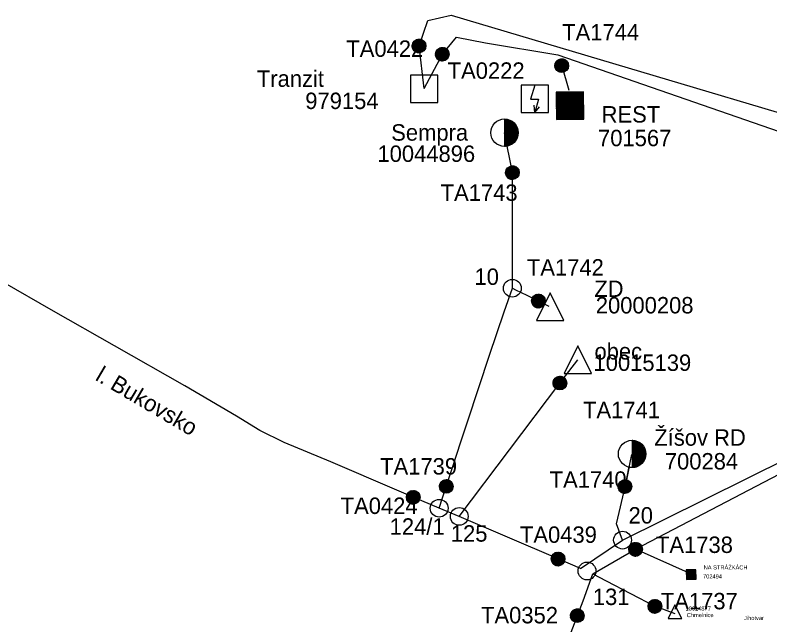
# Model space of a CAD drawing. Extents: x -749194 to -734612, y -1146817 to -1138558.
# Drawn here: x -738789 to -736032, y -1144443 to -1142216 of the extents above; entities that cross this region are included whole.
import ezdxf

# ---------------------------------------------------------------- set-up
doc = ezdxf.new("R2010")
doc.units = 0
for name, color, linetype in [('Default', 7, 'Continuous'), ('Vrstva 1', 7, 'Continuous'), ('Vrstva 2', 7, 'Continuous'), ('Vrstva 20', 7, 'Continuous'), ('Vrstva 3', 7, 'Continuous'), ('Vrstva 4', 7, 'Continuous'), ('Vrstva 44', 7, 'Continuous'), ('Vrstva 47', 7, 'Continuous'), ('Vrstva 5', 7, 'Continuous')]:
    doc.layers.add(name, color=color, linetype=linetype)

# ---------------------------------------------------------------- blocks, each defined once
blk = doc.blocks.new('PS705')
at = {"layer": 'Vrstva 47'}
for points in [[(50, 50), (-50, 50)], [(-50, 50), (-50, -50)], [(0, 50), (-15.8, -0.8)], [(50, -50), (50, 50)], [(-15.8, -0.8), (14.2, -0.8)], [(0, -50), (-2.8, -22.8)], [(14.2, -0.8), (0, -50)], [(-50, -50), (50, -50)], [(0, -50), (17.3, -28.3)]]:
    blk.add_lwpolyline(points, dxfattribs=at)
blk = doc.blocks.new('PS400')
at = {"layer": 'Default'}
for p, q in [((-25, 0.1), (-0.1, 25)), ((-24.9, -1.2), (1.2, 24.9)), ((-24.9, 1.6), (-1.6, 24.9)), ((-24.8, -2.6), (2.6, 24.8)), ((-24.8, 3.2), (-3.2, 24.8)), ((-24.7, -3.8), (3.8, 24.7)), ((-24.5, -5), (5, 24.5)), ((-24.5, 4.9), (-4.9, 24.5)), ((-24.2, -6.2), (6.2, 24.2)), ((-24.1, 6.7), (-6.7, 24.1)), ((-23.9, -7.3), (7.3, 23.9)), ((-23.6, -8.3), (8.3, 23.6)), ((-23.4, 8.8), (-8.8, 23.4)), ((-23.2, -9.4), (9.4, 23.2)), ((-22.7, -10.3), (10.3, 22.7)), ((-22.3, -11.3), (11.3, 22.3)), ((-22.3, 11.3), (-11.3, 22.3)), ((-21.8, -12.2), (12.2, 21.8)), ((-21.3, -13.1), (13.1, 21.3)), ((-20.7, -14), (14, 20.7)), ((-20.1, -14.8), (14.8, 20.1)), ((-19.9, 15.2), (-15.2, 19.9)), ((-19.5, -15.6), (15.6, 19.5)), ((-18.9, -16.4), (16.4, 18.9)), ((-18.2, -17.1), (17.1, 18.2)), ((-17.5, -17.8), (17.8, 17.5)), ((-16.8, -18.5), (18.5, 16.8)), ((-16, -19.2), (19.2, 16)), ((-15.2, -19.8), (19.8, 15.2)), ((-14.4, -20.4), (20.4, 14.4)), ((-13.6, -21), (21, 13.6)), ((-12.7, -21.5), (21.5, 12.7)), ((-11.8, -22), (22, 11.8)), ((-10.8, -22.5), (22.5, 10.8)), ((-9.9, -22.9), (22.9, 9.9)), ((-8.9, -23.4), (23.4, 8.9)), ((-7.8, -23.7), (23.7, 7.8)), ((-6.7, -24.1), (24.1, 6.7)), ((-5.6, -24.3), (24.3, 5.6)), ((-4.4, -24.6), (24.6, 4.4)), ((-3.2, -24.8), (24.8, 3.2)), ((-1.9, -24.9), (24.9, 1.9)), ((-0.6, -25), (25, 0.6)), ((0.8, -25), (25, -0.8)), ((2.3, -24.9), (24.9, -2.3)), ((4, -24.7), (24.7, -4)), ((5.7, -24.3), (24.3, -5.7)), ((7.7, -23.8), (23.8, -7.7)), ((10, -22.9), (22.9, -10)), ((12.9, -21.4), (21.4, -12.9))]:
    blk.add_line(p, q, dxfattribs=at)
blk.add_circle((0, 0), 25, dxfattribs=at)
blk = doc.blocks.new('PS440')
at = {"layer": 'Default'}
for p, q in [((-25, 0.1), (-0.1, 25)), ((-24.9, -1.2), (1.2, 24.9)), ((-24.9, 1.6), (-1.6, 24.9)), ((-24.8, -2.6), (2.6, 24.8)), ((-24.8, 3.2), (-3.2, 24.8)), ((-24.7, -3.8), (3.8, 24.7)), ((-24.5, -5), (5, 24.5)), ((-24.5, 4.9), (-4.9, 24.5)), ((-24.2, -6.2), (6.2, 24.2)), ((-24.1, 6.7), (-6.7, 24.1)), ((-23.9, -7.3), (7.3, 23.9)), ((-23.6, -8.3), (8.3, 23.6)), ((-23.4, 8.8), (-8.8, 23.4)), ((-23.2, -9.4), (9.4, 23.2)), ((-22.7, -10.3), (10.3, 22.7)), ((-22.3, -11.3), (11.3, 22.3)), ((-22.3, 11.3), (-11.3, 22.3)), ((-21.8, -12.2), (12.2, 21.8)), ((-21.3, -13.1), (13.1, 21.3)), ((-20.7, -14), (14, 20.7)), ((-20.1, -14.8), (14.8, 20.1)), ((-19.9, 15.2), (-15.2, 19.9)), ((-19.5, -15.6), (15.6, 19.5)), ((-18.9, -16.4), (16.4, 18.9)), ((-18.2, -17.1), (17.1, 18.2)), ((-17.5, -17.8), (17.8, 17.5)), ((-16.8, -18.5), (18.5, 16.8)), ((-16, -19.2), (19.2, 16)), ((-15.2, -19.8), (19.8, 15.2)), ((-14.4, -20.4), (20.4, 14.4)), ((-13.6, -21), (21, 13.6)), ((-12.7, -21.5), (21.5, 12.7)), ((-11.8, -22), (22, 11.8)), ((-10.8, -22.5), (22.5, 10.8)), ((-9.9, -22.9), (22.9, 9.9)), ((-8.9, -23.4), (23.4, 8.9)), ((-7.8, -23.7), (23.7, 7.8)), ((-6.7, -24.1), (24.1, 6.7)), ((-5.6, -24.3), (24.3, 5.6)), ((-4.4, -24.6), (24.6, 4.4)), ((-3.2, -24.8), (24.8, 3.2)), ((-1.9, -24.9), (24.9, 1.9)), ((-0.6, -25), (25, 0.6)), ((0.8, -25), (25, -0.8)), ((2.3, -24.9), (24.9, -2.3)), ((4, -24.7), (24.7, -4)), ((5.7, -24.3), (24.3, -5.7)), ((7.7, -23.8), (23.8, -7.7)), ((10, -22.9), (22.9, -10)), ((12.9, -21.4), (21.4, -12.9))]:
    blk.add_line(p, q, dxfattribs=at)
blk.add_circle((0, 0), 25, dxfattribs=at)
blk = doc.blocks.new('PS820')
at = {"layer": 'Vrstva 2'}
blk.add_circle((0, 0), 32.5, dxfattribs=at)
blk = doc.blocks.new('PS680')
at = {"layer": 'Vrstva 44'}
for points in [[(0, 25), (-25, -25)], [(25, -25), (0, 25)], [(-25, -25), (25, -25)]]:
    blk.add_lwpolyline(points, dxfattribs=at)
blk = doc.blocks.new('PS630')
at = {"layer": 'Default'}
for p, q in [((-16.6, -14.9), (17.1, 18.7)), ((-16.6, -13.5), (15.7, 18.7)), ((-16.6, -12.1), (14.2, 18.7)), ((-16.6, -10.7), (12.8, 18.7)), ((-16.6, -9.3), (11.4, 18.7)), ((-16.6, -7.9), (10, 18.7)), ((-16.6, -6.5), (8.6, 18.7)), ((-16.6, -5), (7.2, 18.7)), ((-16.6, -3.6), (5.8, 18.7)), ((-16.6, -2.2), (4.3, 18.7)), ((-16.6, -0.8), (2.9, 18.7)), ((-16.6, 0.6), (1.5, 18.7)), ((-16.6, 2), (0.1, 18.7)), ((-16.6, 3.4), (-1.3, 18.7)), ((-16.6, 4.9), (-2.7, 18.7)), ((-16.6, 6.3), (-4.1, 18.7)), ((-16.6, 7.7), (-5.6, 18.7)), ((-16.6, 9.1), (-7, 18.7)), ((-16.6, 10.5), (-8.4, 18.7)), ((-16.6, 11.9), (-9.8, 18.7)), ((-16.6, 13.3), (-11.2, 18.7)), ((-16.6, 14.8), (-12.6, 18.7)), ((-16.6, 16.2), (-14, 18.7)), ((-16.6, 17.6), (-15.5, 18.7)), ((-16.5, -16.3), (18.4, 18.6)), ((-15.1, -16.3), (18.4, 17.2)), ((-13.7, -16.3), (18.4, 15.8)), ((-12.3, -16.3), (18.4, 14.4)), ((-10.9, -16.3), (18.4, 13)), ((-9.4, -16.3), (18.4, 11.6)), ((-8, -16.3), (18.4, 10.2)), ((-6.6, -16.3), (18.4, 8.7)), ((-5.2, -16.3), (18.4, 7.3)), ((-3.8, -16.3), (18.4, 5.9)), ((-2.4, -16.3), (18.4, 4.5)), ((-1, -16.3), (18.4, 3.1)), ((0.5, -16.3), (18.4, 1.7)), ((1.9, -16.3), (18.4, 0.3)), ((3.3, -16.3), (18.4, -1.2)), ((4.7, -16.3), (18.4, -2.6)), ((6.1, -16.3), (18.4, -4)), ((7.5, -16.3), (18.4, -5.4)), ((8.9, -16.3), (18.4, -6.8)), ((10.4, -16.3), (18.4, -8.2)), ((11.8, -16.3), (18.4, -9.6)), ((13.2, -16.3), (18.4, -11.1)), ((14.6, -16.3), (18.4, -12.5)), ((16, -16.3), (18.4, -13.9)), ((17.4, -16.3), (18.4, -15.3))]:
    blk.add_line(p, q, dxfattribs=at)
for points in [[(-16.6, 18.7), (-16.6, -16.3)], [(18.4, 18.7), (-16.6, 18.7)], [(-16.6, 18.7), (-16.6, -16.3)], [(18.4, -16.3), (18.4, 18.7)], [(-16.6, -16.3), (18.4, -16.3)]]:
    blk.add_lwpolyline(points, dxfattribs=at)
blk = doc.blocks.new('PS615')
at = {"layer": 'Default'}
for p, q in [((0, 49.1), (0.9, 50)), ((0, 46.3), (3.6, 49.9)), ((0, 47.7), (2.3, 49.9)), ((0, 44.8), (4.9, 49.8)), ((0, 43.4), (6.2, 49.6)), ((0, 42), (7.4, 49.4)), ((0, 40.6), (8.7, 49.2)), ((0, 39.2), (9.8, 49)), ((0, 37.8), (11, 48.8)), ((0, 36.4), (12.1, 48.5)), ((0, 34.9), (13.3, 48.2)), ((0, 33.5), (14.4, 47.9)), ((0, 32.1), (15.4, 47.6)), ((0, 30.7), (16.5, 47.2)), ((0, 29.3), (17.5, 46.8)), ((0, 27.9), (18.6, 46.4)), ((0, 26.5), (19.6, 46)), ((0, 25), (20.5, 45.6)), ((0, 23.6), (21.5, 45.1)), ((0, 22.2), (22.5, 44.7)), ((0, 20.8), (23.4, 44.2)), ((0, 19.4), (24.3, 43.7)), ((0, 18), (25.2, 43.2)), ((0, 16.6), (26.1, 42.6)), ((0, 15.1), (27, 42.1)), ((0, 13.7), (27.8, 41.5)), ((0, 12.3), (28.7, 41)), ((0, 10.9), (29.5, 40.4)), ((0, 9.5), (30.3, 39.8)), ((0, 8.1), (31.1, 39.2)), ((0, 6.7), (31.9, 38.5)), ((0, 5.2), (32.6, 37.9)), ((0, 3.8), (33.4, 37.2)), ((0, 2.4), (34.1, 36.5)), ((0, 1), (34.9, 35.9)), ((0, -0.4), (35.6, 35.1)), ((0, -1.8), (36.3, 34.4)), ((0, -3.2), (36.9, 33.7)), ((0, -4.7), (37.6, 32.9)), ((0, -6.1), (38.3, 32.2)), ((0, -7.5), (38.9, 31.4)), ((0, -8.9), (39.5, 30.6)), ((0, -10.3), (40.1, 29.8)), ((0, -11.7), (40.7, 29)), ((0, -13.1), (41.3, 28.2)), ((0, -14.6), (41.9, 27.3)), ((0, -16), (42.4, 26.5)), ((0, -17.4), (43, 25.6)), ((0, -18.8), (43.5, 24.7)), ((0, -20.2), (44, 23.8)), ((0, -21.6), (44.5, 22.8)), ((0, -23), (44.9, 21.9)), ((0, -24.5), (45.4, 20.9)), ((0, -25.9), (45.8, 20)), ((0, -27.3), (46.3, 19)), ((0, -28.7), (46.7, 18)), ((0, -30.1), (47, 16.9)), ((0, -31.5), (47.4, 15.9)), ((0, -32.9), (47.8, 14.8)), ((0, -34.4), (48.1, 13.7)), ((0, -35.8), (48.4, 12.6)), ((0, -37.2), (48.7, 11.5)), ((0, -38.6), (48.9, 10.3)), ((0, -40), (49.2, 9.1)), ((0, -41.4), (49.4, 7.9)), ((0, -42.8), (49.5, 6.7)), ((0, -44.3), (49.7, 5.4)), ((0, -45.7), (49.8, 4.2)), ((0, -47.1), (49.9, 2.8)), ((0, -48.5), (50, 1.5)), ((0, -49.9), (50, 0.1)), ((1.3, -50), (50, -1.3)), ((2.8, -49.9), (49.9, -2.8)), ((4.3, -49.8), (49.8, -4.3)), ((5.9, -49.6), (49.6, -5.9)), ((7.6, -49.4), (49.4, -7.6)), ((9.3, -49.1), (49.1, -9.3)), ((11.1, -48.8), (48.8, -11.1)), ((12.9, -48.3), (48.3, -12.9)), ((14.9, -47.7), (47.7, -14.9)), ((17.1, -47), (47, -17.1)), ((19.4, -46.1), (46.1, -19.4)), ((22, -44.9), (44.9, -22)), ((25, -43.3), (43.3, -25)), ((28.9, -40.8), (40.8, -28.9))]:
    blk.add_line(p, q, dxfattribs=at)
blk.add_lwpolyline([(0, 50), (0, -50)], dxfattribs=at)
blk.add_circle((0, 0), 50, dxfattribs=at)
blk = doc.blocks.new('PS685')
at = {"layer": 'Vrstva 44'}
for points in [[(-0.1, 50.1), (-50.1, -49.9)], [(49.9, -49.9), (-0.1, 50.1)], [(-50.1, -49.9), (49.9, -49.9)]]:
    blk.add_lwpolyline(points, dxfattribs=at)
blk = doc.blocks.new('PS656')
at = {"layer": 'Vrstva 20'}
for points in [[(49.9, 50.1), (-50.1, 50.1)], [(-50.1, 50.1), (-50.1, -49.9)], [(49.9, -49.9), (49.9, 50.1)], [(-50.1, -49.9), (49.9, -49.9)]]:
    blk.add_lwpolyline(points, dxfattribs=at)
blk = doc.blocks.new('PS636')
at = {"layer": 'Default'}
for p, q in [((-50.6, -54.9), (49, 44.7)), ((-50.6, -53.5), (47.6, 44.7)), ((-50.6, -52), (46.2, 44.7)), ((-50.6, -50.6), (44.7, 44.7)), ((-50.6, -49.2), (43.3, 44.7)), ((-50.6, -47.8), (41.9, 44.7)), ((-50.6, -46.4), (40.5, 44.7)), ((-50.6, -45), (39.1, 44.7)), ((-50.6, -43.6), (37.7, 44.7)), ((-50.6, -42.1), (36.3, 44.7)), ((-50.6, -40.7), (34.8, 44.7)), ((-50.6, -39.3), (33.4, 44.7)), ((-50.6, -37.9), (32, 44.7)), ((-50.6, -36.5), (30.6, 44.7)), ((-50.6, -35.1), (29.2, 44.7)), ((-50.6, -33.7), (27.8, 44.7)), ((-50.6, -32.2), (26.4, 44.7)), ((-50.6, -30.8), (24.9, 44.7)), ((-50.6, -29.4), (23.5, 44.7)), ((-50.6, -28), (22.1, 44.7)), ((-50.6, -26.6), (20.7, 44.7)), ((-50.6, -25.2), (19.3, 44.7)), ((-50.6, -23.8), (17.9, 44.7)), ((-50.6, -22.3), (16.5, 44.7)), ((-50.6, -20.9), (15, 44.7)), ((-50.6, -19.5), (13.6, 44.7)), ((-50.6, -18.1), (12.2, 44.7)), ((-50.6, -16.7), (10.8, 44.7)), ((-50.6, -15.3), (9.4, 44.7)), ((-50.6, -13.9), (8, 44.7)), ((-50.6, -12.4), (6.6, 44.7)), ((-50.6, -11), (5.1, 44.7)), ((-50.6, -9.6), (3.7, 44.7)), ((-50.6, -8.2), (2.3, 44.7)), ((-50.6, -6.8), (0.9, 44.7)), ((-50.6, -5.4), (-0.5, 44.7)), ((-50.6, -4), (-1.9, 44.7)), ((-50.6, -2.5), (-3.3, 44.7)), ((-50.6, -1.1), (-4.8, 44.7)), ((-50.6, 0.3), (-6.2, 44.7)), ((-50.6, 1.7), (-7.6, 44.7)), ((-50.6, 3.1), (-9, 44.7)), ((-50.6, 4.5), (-10.4, 44.7)), ((-50.6, 5.9), (-11.8, 44.7)), ((-50.6, 7.4), (-13.2, 44.7)), ((-50.6, 8.8), (-14.7, 44.7)), ((-50.6, 10.2), (-16.1, 44.7)), ((-50.6, 11.6), (-17.5, 44.7)), ((-50.6, 13), (-18.9, 44.7)), ((-50.6, 14.4), (-20.3, 44.7)), ((-50.6, 15.8), (-21.7, 44.7)), ((-50.6, 17.3), (-23.1, 44.7)), ((-50.6, 18.7), (-24.6, 44.7)), ((-50.6, 20.1), (-26, 44.7)), ((-50.6, 21.5), (-27.4, 44.7)), ((-50.6, 22.9), (-28.8, 44.7)), ((-50.6, 24.3), (-30.2, 44.7)), ((-50.6, 25.7), (-31.6, 44.7)), ((-50.6, 27.2), (-33, 44.7)), ((-50.6, 28.6), (-34.5, 44.7)), ((-50.6, 30), (-35.9, 44.7)), ((-50.6, 31.4), (-37.3, 44.7)), ((-50.6, 32.8), (-38.7, 44.7)), ((-50.6, 34.2), (-40.1, 44.7)), ((-50.6, 35.6), (-41.5, 44.7)), ((-50.6, 37.1), (-42.9, 44.7)), ((-50.6, 38.5), (-44.3, 44.7)), ((-50.6, 39.9), (-45.8, 44.7)), ((-50.6, 41.3), (-47.2, 44.7)), ((-50.6, 42.7), (-48.6, 44.7)), ((-50.6, 44.1), (-50, 44.7)), ((-49.6, -55.3), (49.4, 43.7)), ((-48.2, -55.3), (49.4, 42.3)), ((-46.8, -55.3), (49.4, 40.9)), ((-45.4, -55.3), (49.4, 39.5)), ((-43.9, -55.3), (49.4, 38.1)), ((-42.5, -55.3), (49.4, 36.6)), ((-41.1, -55.3), (49.4, 35.2)), ((-39.7, -55.3), (49.4, 33.8)), ((-38.3, -55.3), (49.4, 32.4)), ((-36.9, -55.3), (49.4, 31)), ((-35.5, -55.3), (49.4, 29.6)), ((-34, -55.3), (49.4, 28.2)), ((-32.6, -55.3), (49.4, 26.7)), ((-31.2, -55.3), (49.4, 25.3)), ((-29.8, -55.3), (49.4, 23.9)), ((-28.4, -55.3), (49.4, 22.5)), ((-27, -55.3), (49.4, 21.1)), ((-25.6, -55.3), (49.4, 19.7)), ((-24.1, -55.3), (49.4, 18.3)), ((-22.7, -55.3), (49.4, 16.8)), ((-21.3, -55.3), (49.4, 15.4)), ((-19.9, -55.3), (49.4, 14)), ((-18.5, -55.3), (49.4, 12.6)), ((-17.1, -55.3), (49.4, 11.2)), ((-15.7, -55.3), (49.4, 9.8)), ((-14.2, -55.3), (49.4, 8.4)), ((-12.8, -55.3), (49.4, 6.9)), ((-11.4, -55.3), (49.4, 5.5)), ((-10, -55.3), (49.4, 4.1)), ((-8.6, -55.3), (49.4, 2.7)), ((-7.2, -55.3), (49.4, 1.3)), ((-5.8, -55.3), (49.4, -0.1)), ((-4.3, -55.3), (49.4, -1.5)), ((-2.9, -55.3), (49.4, -2.9)), ((-1.5, -55.3), (49.4, -4.4)), ((-0.1, -55.3), (49.4, -5.8)), ((1.3, -55.3), (49.4, -7.2)), ((2.7, -55.3), (49.4, -8.6)), ((4.1, -55.3), (49.4, -10)), ((5.6, -55.3), (49.4, -11.4)), ((7, -55.3), (49.4, -12.8)), ((8.4, -55.3), (49.4, -14.3)), ((9.8, -55.3), (49.4, -15.7)), ((11.2, -55.3), (49.4, -17.1)), ((12.6, -55.3), (49.4, -18.5)), ((14, -55.3), (49.4, -19.9)), ((15.5, -55.3), (49.4, -21.3)), ((16.9, -55.3), (49.4, -22.7)), ((18.3, -55.3), (49.4, -24.2)), ((19.7, -55.3), (49.4, -25.6)), ((21.1, -55.3), (49.4, -27)), ((22.5, -55.3), (49.4, -28.4)), ((23.9, -55.3), (49.4, -29.8)), ((25.4, -55.3), (49.4, -31.2)), ((26.8, -55.3), (49.4, -32.6)), ((28.2, -55.3), (49.4, -34.1)), ((29.6, -55.3), (49.4, -35.5)), ((31, -55.3), (49.4, -36.9)), ((32.4, -55.3), (49.4, -38.3)), ((33.8, -55.3), (49.4, -39.7)), ((35.3, -55.3), (49.4, -41.1)), ((36.7, -55.3), (49.4, -42.5)), ((38.1, -55.3), (49.4, -44)), ((39.5, -55.3), (49.4, -45.4)), ((40.9, -55.3), (49.4, -46.8)), ((42.3, -55.3), (49.4, -48.2)), ((43.7, -55.3), (49.4, -49.6)), ((45.2, -55.3), (49.4, -51)), ((46.6, -55.3), (49.4, -52.4)), ((48, -55.3), (49.4, -53.9))]:
    blk.add_line(p, q, dxfattribs=at)
for points in [[(-50.6, 44.7), (-50.6, -55.3)], [(49.4, 44.7), (-50.6, 44.7)], [(-50.6, 44.7), (-50.6, -55.3)], [(49.4, -55.3), (49.4, 44.7)], [(-50.6, -55.3), (49.4, -55.3)]]:
    blk.add_lwpolyline(points, dxfattribs=at)

msp = doc.modelspace()

# ---------------------------------------------------------------- linework, layer by layer
at = {"layer": 'Vrstva 1'}
for points in [[(-737281.2, -1142235.6), (-737196, -1142216), (-735166, -1142820.5)], [(-737313.2, -1142328.7), (-737281.2, -1142235.6)], [(-737228.1, -1142358.7), (-737177, -1142296.1)], [(-737177, -1142296.1), (-737070.4, -1142317.6), (-736806.2, -1142360.9)], [(-737294.4, -1142484.2), (-737313.2, -1142328.7)], [(-737294, -1142484.2), (-737228.1, -1142358.7)], [(-736806.2, -1142360.9), (-735438.9, -1142834.9)], [(-736792, -1142400.7), (-736766.6, -1142490.2)], [(-736971.9, -1142791.4), (-737001.2, -1142645.4)], [(-737334.6, -1143976.8), (-737394.6, -1143951.2), (-737635.9, -1143848.1), (-737805.3, -1143777.2), (-737894.7, -1143733.3), (-737980.4, -1143680.5), (-738169, -1143569.6), (-738425.3, -1143423.7), (-738648.7, -1143297.5), (-738835.1, -1143190), (-738901.3, -1143150.6), (-738936.5, -1143130.2), (-738970.4, -1143109.9), (-739088.8, -1143046.1), (-739260.1, -1142910.3), (-739340.7, -1142846), (-739424.3, -1142779.4), (-739498, -1142714.4), (-739571.1, -1142649.7), (-739571.2, -1142649.6)], [(-736972.4, -1143213.6), (-736971.9, -1142791.4)], [(-736522.5, -1144166.6), (-735941.9, -1143863.1), (-735673.8, -1143252.7), (-734966.1, -1143033.7), (-734831.4, -1142984.5)], [(-736569.9, -1144133.5), (-735964, -1143832.7), (-735925.7, -1143729.5), (-735872.7, -1143602.7), (-735771, -1143349), (-735719.1, -1143221.8), (-735384.5, -1143105.6)], [(-737213.6, -1143937.5), (-737187.4, -1143857.5), (-737161.2, -1143777.7), (-737135, -1143697.9), (-737056.3, -1143458.5), (-737029.1, -1143379.2), (-737001.9, -1143299.9), (-736972.4, -1143213.6), (-736972.4, -1143213.6)], [(-736972.4, -1143213.6), (-736961.2, -1143218.9), (-736919.7, -1143239.2), (-736877.4, -1143259.9), (-736877.3, -1143259.9), (-736877.3, -1143259.9)], [(-736877.3, -1143259.9), (-736838.6, -1143278.6)], [(-736798.6, -1143559.9), (-736733, -1143474.6)], [(-737166.3, -1144046.9), (-736798.6, -1143559.9)], [(-736560.9, -1143937.8), (-736535.5, -1143820.6)], [(-736569.9, -1144133.5), (-736569.9, -1144133.7), (-736592.5, -1144073.5), (-736558.5, -1143933.7), (-736546, -1143864.7), (-736560.9, -1143937.8)], [(-737239.7, -1144017.2), (-737239.7, -1144017.2), (-737213.6, -1143937.5)], [(-737239.7, -1144017.2), (-737334.6, -1143976.8)], [(-737166.3, -1144046.9), (-737239.7, -1144017.2)], [(-736805.5, -1144202.2), (-737166.3, -1144046.9)], [(-736723.3, -1144237.1), (-736569.9, -1144133.7), (-736569.9, -1144133.5)], [(-736678.1, -1144257.1), (-736522.4, -1144166.7)], [(-736318.3, -1144258), (-736522.5, -1144166.6)], [(-736723.3, -1144237.1), (-736805.5, -1144202.2)], [(-736735, -1144409.5), (-736735.9, -1144411.9), (-736714, -1144355), (-736678.1, -1144257.1)], [(-736678.1, -1144257), (-736630.2, -1144282.2), (-736451.8, -1144375)], [(-736378.1, -1144403.1), (-736451.8, -1144375)], [(-736758, -1144469.4), (-736758, -1144469.4), (-736739.4, -1144422), (-736735, -1144409.5)]]:
    msp.add_lwpolyline(points, dxfattribs=at)

# ---------------------------------------------------------------- block references
at = {"layer": 'Vrstva 2'}
for name, p, rotation in [('PS440', (-737313.2, -1142328.7), 83.04929997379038), ('PS440', (-737228.1, -1142358.7), 83.04929997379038), ('PS440', (-736792, -1142400.7), 62.20457500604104), ('PS440', (-736971.9, -1142791.4), 79.44574998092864), ('PS440', (-736877.3, -1143259.9), -21.951630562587), ('PS440', (-736798.6, -1143559.9), 60.2482583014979), ('PS440', (-737213.6, -1143937.5), 71.84959440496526), ('PS440', (-736560.9, -1143937.8), 79.76966111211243), ('PS440', (-737334.6, -1143976.8), -23.072616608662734), ('PS400', (-736522.4, -1144166.7), -81.98175274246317), ('PS400', (-736805.5, -1144202.2), -23.091038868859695), ('PS440', (-736451.8, -1144375), -24.8498583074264), ('PS400', (-736735, -1144409.5), 64.13117499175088)]:
    msp.add_blockref(name, p, dxfattribs=dict(at, rotation=rotation))
at = {"layer": 'Vrstva 3'}
for name, p in [('PS656', (-737294.4, -1142485.7)), ('PS615', (-737001.2, -1142645.4)), ('PS685', (-736834.5, -1143281)), ('PS685', (-736733, -1143474.6)), ('PS615', (-736535.1, -1143818.8)), ('PS680', (-736378.8, -1144395))]:
    msp.add_blockref(name, p, dxfattribs=at)
for name, p, rotation in [('PS636', (-736761.3, -1142541.2), 0.5058555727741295), ('PS630', (-736318.3, -1144258), -179.0550750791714)]:
    msp.add_blockref(name, p, dxfattribs=dict(at, rotation=rotation))
at = {"layer": 'Vrstva 4'}
msp.add_blockref('PS705', (-736890.5, -1142522.3), dxfattribs=at)
at = {"layer": 'Vrstva 5'}
for p, rotation in [((-736972.4, -1143213.6), 71.09295834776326), ((-737239.7, -1144017.2), -22.01006116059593), ((-737166.3, -1144046.9), -22.01006113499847), ((-736569.9, -1144133.5), 21.56880283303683), ((-736699.6, -1144246.3), 48.22333052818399)]:
    msp.add_blockref('PS820', p, dxfattribs=dict(at, rotation=rotation))

# ---------------------------------------------------------------- texts
at = {"layer": 'Vrstva 1'}
msp.add_text('l. Bukovsko', height=60, rotation=329.54, dxfattribs=at).set_placement((-738499.3, -1143547.1))
at = {"layer": 'Vrstva 2'}
for s, p in [('TA1744', (-736790.3, -1142308.7)), ('TA0422', (-737578.9, -1142368.4)), ('TA0222', (-737208.7, -1142448.6)), ('TA1743', (-737234.3, -1142894.4)), ('TA1742', (-736919.2, -1143167.4)), ('TA1741', (-736714.1, -1143688.1)), ('TA1739', (-737455.4, -1143893.9)), ('TA1740', (-736836.1, -1143942.4)), ('TA0424', (-737599.5, -1144038)), ('TA0439', (-736944.6, -1144143.4)), ('TA1738', (-736447.7, -1144180.4)), ('TA1737', (-736430, -1144386.2)), ('TA0352', (-737086.7, -1144437.5))]:
    msp.add_text(s, height=60, dxfattribs=at).set_placement(p)
at = {"layer": 'Vrstva 3'}
for s, height, p in [('Tranzit', 60, (-737905.7, -1142478)), ('979154', 60, (-737728.8, -1142559.1)), ('REST', 60, (-736646.3, -1142608.4)), ('Sempra', 60, (-737414.9, -1142674.6)), ('701567', 60, (-736659.4, -1142694.8)), ('10044896', 60, (-737465.2, -1142752.2)), ('ZD', 60, (-736673.1, -1143245.4)), ('20000208', 60, (-736667.6, -1143305.6)), ('obec', 60, (-736672.4, -1143474)), ('10015139', 60, (-736676, -1143515.5)), ('Žíšov RD', 60, (-736454, -1143788.7)), ('700284', 60, (-736415.4, -1143875.5)), ('NA STRÁŽKÁCH', 15, (-736273.5, -1144240.7)), ('702494', 15, (-736275.9, -1144273.6)), ('10014877', 15, (-736339.6, -1144390.9)), ('Chmelnice', 15, (-736335.3, -1144414.8)), ('Jihotvar', 15, (-736126.1, -1144425.3))]:
    msp.add_text(s, height=height, dxfattribs=at).set_placement(p)
at = {"layer": 'Vrstva 5'}
for s, p in [('10', (-737110.7, -1143201.4)), ('20', (-736548, -1144073)), ('124/1', (-737420.5, -1144113.8)), ('125', (-737197.2, -1144139.1)), ('131', (-736678.4, -1144370.6))]:
    msp.add_text(s, height=60, dxfattribs=at).set_placement(p)

doc.saveas('drawing.dxf')
